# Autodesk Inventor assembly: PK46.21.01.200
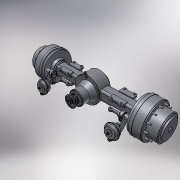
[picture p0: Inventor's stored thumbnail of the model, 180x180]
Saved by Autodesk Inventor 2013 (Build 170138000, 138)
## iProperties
Created: 2005-03
Part Number: PK46.21.01.200
Document SubType Name: Assembly
Designer: salex
Manufacturer: Standard
Standards Organization: Custom
Author: salex
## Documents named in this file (12)
- C:\Product Design Suite 2013 Test Drive\Dynamic Simulation\Workspace\Assy, Chassis, Front\PK46.21.01.200.iam
- C:\Product Design Suite 2013 Test Drive\Dynamic Simulation\Workspace\Assy, Chassis, Front\PK46.42.00.001.ipt
- C:\Product Design Suite 2013 Test Drive\Dynamic Simulation\Workspace\Assy, Chassis, Front\PK46.42.00.020.iam
- C:\Product Design Suite 2013 Test Drive\Dynamic Simulation\Workspace\Assy, Chassis, Front\PK46.21.01.081.ipt
- C:\Product Design Suite 2013 Test Drive\Dynamic Simulation\Workspace\Assy, Chassis, Front\PK46.21.01.082.ipt
- C:\Product Design Suite 2013 Test Drive\Dynamic Simulation\Workspace\Assy, Chassis, Front\PK46.21.01.083.ipt
- C:\Product Design Suite 2013 Test Drive\Dynamic Simulation\Workspace\Assy, Chassis, Front\PK46.21.01.084.ipt
- C:\Product Design Suite 2013 Test Drive\Dynamic Simulation\Workspace\Assy, Chassis, Front\PK46.21.01.085.ipt
- C:\Product Design Suite 2013 Test Drive\Dynamic Simulation\Workspace\Assy, Chassis, Front\PK46.21.01.086.ipt
- C:\Product Design Suite 2013 Test Drive\Dynamic Simulation\Workspace\Assy, Chassis, Front\PK46.21.01.087.ipt
- C:\Product Design Suite 2013 Test Drive\Dynamic Simulation\Workspace\Assy, Chassis, Front\PK46.21.01.083_MIR.ipt
- C:\Product Design Suite 2013 Test Drive\Dynamic Simulation\Workspace\Assy, Chassis, Front\PK46.21.01.088.ipt
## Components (16 placed, 11 different names)
1. PK46.21.01.081:1 — Вставка:1, Вставка:2, Заподлицо:1, Заподлицо:2, Угол:5, Совмещение:38, Совмещение:39, Угол:10, Совмещение:40, Mate:43
2. PK46.21.01.082:1 — Вставка:2, Заподлицо:2, Совмещение:1, Угол:4, Угол:8, Mate:42
3. PK46.21.01.082:2 — Вставка:1, Заподлицо:1
4. PK46.21.01.083:1 — Угол:5, Mate:42, Mate:43
5. PK46.21.01.084:1
6. PK46.21.01.084:2 — Совмещение:41
7. PK46.21.01.085:1
8. PK46.21.01.085:2
9. PK46.21.01.086:1
10. PK46.21.01.086:2
11. PK46.21.01.087:1
12. PK46.21.01.083_MIR:1
13. PK46.42.00.001:1 — Угол:8, Угол:9
14. PK46.42.00.001:2 — Угол:9
15. PK46.42.00.020:1 [sub-assembly] — Совмещение:38, Совмещение:39, Угол:10, Совмещение:40
16. PK46.21.01.088:1 — Совмещение:41
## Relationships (16: Mate 7, Angle 5, Insert 2, Flush 2)
- Вставка:1 [Insert]: PK46.21.01.081:1 ↔ PK46.21.01.082:2
- Вставка:2 [Insert]: PK46.21.01.081:1 ↔ PK46.21.01.082:1
- Заподлицо:1 [Flush]: PK46.21.01.081:1 ↔ PK46.21.01.082:2
- Заподлицо:2 [Flush]: PK46.21.01.081:1 ↔ PK46.21.01.082:1
- Совмещение:1 [Mate]: PK46.21.01.082:1
- Угол:4 [Angle]: PK46.21.01.082:1
- Угол:5 [Angle]: PK46.21.01.081:1 ↔ PK46.21.01.083:1
- Угол:8 [Angle]: PK46.21.01.082:1 ↔ PK46.42.00.001:1
- Угол:9 [Angle]: PK46.42.00.001:1 ↔ PK46.42.00.001:2
- Совмещение:38 [Mate]: PK46.21.01.081:1 ↔ PK46.42.00.020:1
- Совмещение:39 [Mate]: PK46.21.01.081:1 ↔ PK46.42.00.020:1
- Угол:10 [Angle]: PK46.21.01.081:1 ↔ PK46.42.00.020:1
- Совмещение:40 [Mate]: PK46.21.01.081:1 ↔ PK46.42.00.020:1
- Совмещение:41 [Mate]: PK46.21.01.084:2 ↔ PK46.21.01.088:1
- Mate:42: PK46.21.01.082:1 ↔ PK46.21.01.083:1
- Mate:43: PK46.21.01.081:1 ↔ PK46.21.01.083:1
